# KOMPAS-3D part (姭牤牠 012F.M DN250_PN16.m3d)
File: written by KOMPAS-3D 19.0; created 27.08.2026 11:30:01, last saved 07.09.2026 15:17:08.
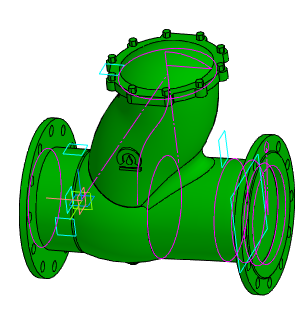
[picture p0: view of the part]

Document properties: Автор: Энергия; Полное имя файла: Z:\3.Личные\kachalov\001_3d для проектировщиков\х.х Тип 012F\012F.M\Клапан 012F.M DN250_PN16.m3d

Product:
- Part/product: (unnamed)  | designation Клапан 012F.M DN250_PN16
    Масса: 180.987

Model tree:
1. Эскиз:1
2. Элемент вращения:1
     Угол 1 = 360
3. Эскиз:2  (with: Элемент вращения:1)
4. Параллельная плоскость:3
5. Эскиз:26
6. Эскиз:30
7. Смещенная плоскость:5
     Расстояние = 150
8. Эскиз:50
9. Эскиз:51
10. Элемент по траектории:1
     Толщина стенки 1 = 1
11. Эскиз:31
12. Эскиз:38  (with: Элемент вращения:1)
13. Параллельная плоскость:4
14. Смещенная плоскость:2  (with: Элемент вращения:1)
     Расстояние = 32
15. Эскиз:39  (with: Элемент вращения:1)
16. Эскиз:40  (with: Элемент вращения:1)
17. Смещенная плоскость:3
     Расстояние = 33
18. Эскиз:42  (with: Элемент вращения:1)
19. Элемент по сечениям:4
20. Элемент вращения:6  (with: Элемент вращения:1)
     Угол 1 = 360
21. Эскиз:10  (with: Элемент вращения:1)
22. Элемент выдавливания:3  (with: Элемент вращения:1)
     Расстояние 2 = 19
23. Массив по концентрической сетке:1  (with: Элемент выдавливания:3, Эскиз:10, Элемент вращения:1)  (12 pattern instances)
     Шаг 2 = 360
24. Эскиз:11  (with: Элемент вращения:1)
25. Элемент выдавливания:4  (with: Элемент вращения:1)
     Расстояние 2 = 19
26. Массив по концентрической сетке:2  (with: Элемент выдавливания:4, Эскиз:11, Элемент вращения:1)  (12 pattern instances)
     Шаг 2 = 360
27. Эскиз:32
28. Элемент выдавливания:13
     Расстояние 1 = 25
29. Эскиз:33  (with: Элемент выдавливания:13)
30. Элемент вращения:7
     Угол 1 = 360
31. Эскиз:34  (with: Элемент вращения:1, Элемент вращения:6)
32. Элемент выдавливания:14  (with: Элемент вращения:6)
     Расстояние 1 = 160; Смещение 1 = 10
33. Скругление:23  (with: Элемент выдавливания:14)
     Радиус = 3
34. Эскиз:35  (with: Элемент выдавливания:14)
35. Элемент выдавливания:15
     Расстояние 1 = 10
36. Эскиз:36  (with: Элемент выдавливания:13)
37. Элемент выдавливания:16
     Расстояние 1 = 15
38. Эскиз:43  (with: Элемент выдавливания:13)
39. Массив по концентрической сетке:3  (with: Элемент выдавливания:16, Эскиз:36, Эскиз:33)  (10 pattern instances)
     Шаг 2 = 360
40. Смещенная плоскость:4
     Расстояние = 130
41. Эскиз:46
42. Элемент выдавливания:20  (with: Элемент по траектории:1)
     Расстояние 2 = 4.23072
43. Эскиз:47  (with: Элемент вращения:1)
44. Эскиз:48  (with: Элемент вращения:1)
45. Элемент выдавливания:22
     Расстояние 2 = 320
46. Эскиз:49  (with: Элемент вращения:1)
47. Скругление:28  (with: Элемент по сечениям:4)
     Радиус = 30
48. Скругление:29  (with: Элемент вращения:6)
     Радиус = 20

Expressions: Dn/2; D/2; D2/2; 360/(2*n); 360/(n*2); D3/2
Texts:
  Клапан 012F.M DN250_PN16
